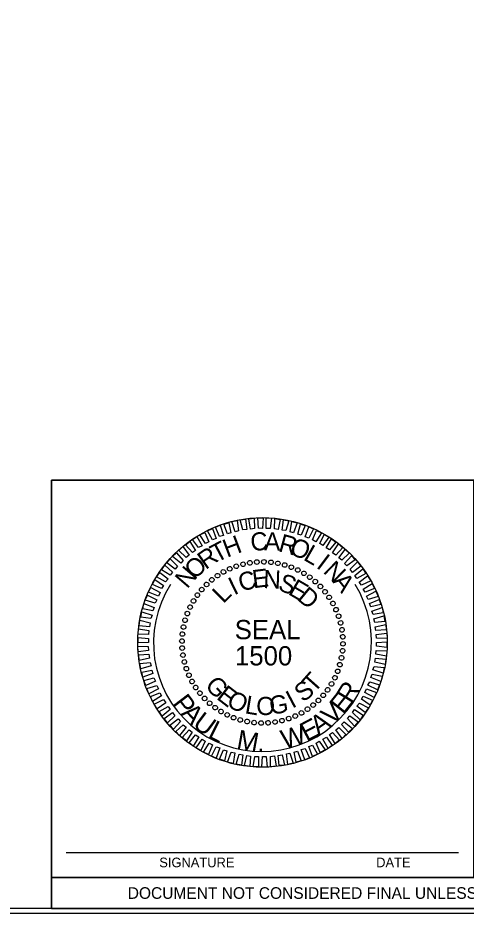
# Model space of a CAD drawing. Extents: x 265553 to 275568, y 168312 to 173522.
# Drawn here: x 273654 to 273933, y 172140 to 172697 of the extents above; entities that cross this region are included whole.
import ezdxf

# ---------------------------------------------------------------- set-up
doc = ezdxf.new("R2010")
doc.units = 0
for name, color, linetype in [('Geotech Sheets and Borders Cell', 7, 'Continuous'), ('Scratch_Level_0', 7, 'Continuous'), ('Scratch_Level_6', 7, 'Continuous'), ('Sheet Plot Border Inside CELL', 7, 'Continuous'), ('Sheet Professional Seal CELL', 7, 'Continuous'), ('Sheet Sticker Exception Certification CELL', 7, 'Continuous')]:
    doc.layers.add(name, color=color, linetype=linetype)

msp = doc.modelspace()

# ---------------------------------------------------------------- linework, layer by layer
at = {"layer": 'Geotech Sheets and Borders Cell'}
msp.add_line((273928.45, 172177.29), (273684.03, 172177.29), dxfattribs=at)
for points in [[(272700.69, 173192.58), (274200.69, 173192.58), (274200.69, 172142.58), (272700.69, 172142.58)], [(273674.76, 172409.27), (273937.73, 172409.27), (273937.73, 172161.9), (273674.76, 172161.9)]]:
    msp.add_lwpolyline(points, close=True, dxfattribs=at)
msp.add_lwpolyline([(274200.69, 172409.27), (273674.76, 172409.27), (273674.76, 172142.58), (274200.69, 172142.58), (274200.69, 172410.73)], dxfattribs=at)
at = {"layer": 'Scratch_Level_0'}
msp.add_ellipse((273806.24, 172308.22), major_axis=(45.09, 51.04), ratio=0.993455, start_param=1.731198, end_param=5.992706, dxfattribs=at)
at = {"layer": 'Scratch_Level_6'}
msp.add_circle((273806.24, 172308.22), 77.7, dxfattribs=at)
msp.add_circle((273806.24, 172308.22), 77.7, dxfattribs=at)
at = {"layer": 'Sheet Plot Border Inside CELL'}
msp.add_lwpolyline([(272545.53, 172139.74), (274213.19, 172139.74), (274213.19, 173195.41), (272545.53, 173195.41)], close=True, dxfattribs=at)
at = {"layer": 'Sheet Professional Seal CELL'}
for p, q in [((273789.84, 172355.72), (273789.84, 172355.72)), ((273794.04, 172356.92), (273794.04, 172356.92)), ((273798.44, 172357.72), (273798.44, 172357.72)), ((273802.74, 172358.32), (273802.74, 172358.32)), ((273807.14, 172358.42), (273807.14, 172358.42)), ((273811.54, 172358.12), (273811.54, 172358.12)), ((273815.84, 172357.42), (273815.84, 172357.42)), ((273820.04, 172356.52), (273820.04, 172356.52)), ((273824.24, 172355.12), (273824.24, 172355.12)), ((273778.14, 172349.82), (273778.14, 172349.82)), ((273781.94, 172352.12), (273781.94, 172352.12)), ((273785.84, 172354.12), (273785.84, 172354.12)), ((273828.24, 172353.32), (273828.24, 172353.32)), ((273832.14, 172351.32), (273832.14, 172351.32)), ((273771.34, 172344.32), (273771.34, 172344.32)), ((273774.64, 172347.32), (273774.64, 172347.32)), ((273835.74, 172348.82), (273835.74, 172348.82)), ((273839.24, 172346.12), (273839.24, 172346.12)), ((273768.34, 172341.22), (273768.34, 172341.22)), ((273842.34, 172343.12), (273842.34, 172343.12)), ((273845.34, 172339.82), (273845.34, 172339.82)), ((273763.14, 172334.12), (273763.14, 172334.12)), ((273765.64, 172337.72), (273765.64, 172337.72)), ((273847.84, 172336.32), (273847.84, 172336.32)), ((273850.14, 172332.52), (273850.14, 172332.52)), ((273761.14, 172330.22), (273761.14, 172330.22)), ((273852.14, 172328.62), (273852.14, 172328.62)), ((273757.94, 172322.02), (273757.94, 172322.02)), ((273759.34, 172326.22), (273759.34, 172326.22)), ((273853.74, 172324.62), (273853.74, 172324.62)), ((273757.04, 172317.82), (273757.04, 172317.82)), ((273854.94, 172320.42), (273854.94, 172320.42)), ((273855.74, 172316.02), (273855.74, 172316.02)), ((273756.34, 172313.52), (273756.34, 172313.52)), ((273856.34, 172311.72), (273856.34, 172311.72)), ((273756.04, 172309.12), (273756.04, 172309.12)), ((273756.14, 172304.72), (273756.14, 172304.72)), ((273856.44, 172307.32), (273856.44, 172307.32)), ((273756.74, 172300.42), (273756.74, 172300.42)), ((273856.14, 172302.92), (273856.14, 172302.92)), ((273757.54, 172296.02), (273757.54, 172296.02)), ((273854.54, 172294.42), (273854.54, 172294.42)), ((273855.44, 172298.62), (273855.44, 172298.62)), ((273758.74, 172291.82), (273758.74, 172291.82)), ((273760.34, 172287.82), (273760.34, 172287.82)), ((273853.14, 172290.22), (273853.14, 172290.22)), ((273762.34, 172283.92), (273762.34, 172283.92)), ((273849.34, 172282.32), (273849.34, 172282.32)), ((273851.34, 172286.22), (273851.34, 172286.22)), ((273764.64, 172280.12), (273764.64, 172280.12)), ((273846.84, 172278.72), (273846.84, 172278.72)), ((273767.14, 172276.62), (273767.14, 172276.62)), ((273770.14, 172273.32), (273770.14, 172273.32)), ((273841.14, 172272.12), (273841.14, 172272.12)), ((273844.14, 172275.22), (273844.14, 172275.22)), ((273773.24, 172270.32), (273773.24, 172270.32)), ((273776.74, 172267.62), (273776.74, 172267.62)), ((273834.34, 172266.62), (273834.34, 172266.62)), ((273837.84, 172269.12), (273837.84, 172269.12)), ((273780.34, 172265.12), (273780.34, 172265.12)), ((273784.24, 172263.12), (273784.24, 172263.12)), ((273788.24, 172261.32), (273788.24, 172261.32)), ((273792.44, 172259.92), (273792.44, 172259.92)), ((273822.64, 172260.72), (273822.64, 172260.72)), ((273826.64, 172262.32), (273826.64, 172262.32)), ((273830.54, 172264.32), (273830.54, 172264.32)), ((273796.64, 172259.02), (273796.64, 172259.02)), ((273800.94, 172258.32), (273800.94, 172258.32)), ((273805.34, 172258.02), (273805.34, 172258.02)), ((273809.74, 172258.12), (273809.74, 172258.12)), ((273814.04, 172258.72), (273814.04, 172258.72)), ((273818.44, 172259.52), (273818.44, 172259.52))]:
    msp.add_line(p, q, dxfattribs=at)
for points in [[(273784.44, 172375.82), (273782.14, 172381.82), (273785.24, 172382.72), (273786.54, 172376.52)], [(273789.24, 172377.12), (273787.14, 172383.42), (273790.54, 172384.12), (273791.34, 172377.62)], [(273794.04, 172378.22), (273792.44, 172384.62), (273795.74, 172384.92), (273796.44, 172378.52)], [(273798.84, 172378.82), (273797.74, 172385.22), (273801.14, 172385.62), (273801.24, 172379.12)], [(273803.84, 172379.32), (273803.34, 172385.82), (273806.64, 172385.72), (273806.24, 172379.22)], [(273808.64, 172379.22), (273808.64, 172385.72), (273811.94, 172385.62), (273811.04, 172379.12)], [(273813.64, 172378.92), (273814.04, 172385.42), (273817.34, 172384.82), (273816.04, 172378.52)], [(273818.44, 172378.12), (273819.34, 172384.52), (273822.64, 172384.02), (273820.84, 172377.82)], [(273823.54, 172377.02), (273824.54, 172383.52), (273827.94, 172382.72), (273825.64, 172376.52)], [(273775.14, 172372.12), (273771.94, 172377.72), (273775.04, 172379.12), (273777.34, 172373.02)], [(273779.54, 172374.22), (273776.94, 172380.02), (273779.94, 172381.22), (273782.04, 172374.82)], [(273828.34, 172375.72), (273829.84, 172381.92), (273832.94, 172380.92), (273830.44, 172375.02)], [(273832.84, 172373.92), (273835.14, 172380.22), (273837.94, 172379.02), (273835.14, 172373.22)], [(273837.34, 172372.02), (273839.84, 172377.92), (273842.94, 172376.52), (273839.54, 172370.92)], [(273766.44, 172367.22), (273762.74, 172372.32), (273765.34, 172374.22), (273768.64, 172368.42)], [(273770.84, 172369.72), (273767.14, 172375.12), (273770.24, 172376.72), (273772.74, 172370.92)], [(273841.94, 172369.72), (273844.64, 172375.42), (273847.64, 172373.72), (273843.84, 172368.52)], [(273845.84, 172367.02), (273849.34, 172372.82), (273851.94, 172370.72), (273848.04, 172365.82)], [(273758.64, 172361.12), (273754.24, 172365.52), (273756.64, 172367.92), (273760.54, 172362.52)], [(273762.64, 172364.22), (273758.34, 172369.02), (273761.04, 172371.12), (273764.54, 172365.52)], [(273849.94, 172364.02), (273853.64, 172369.52), (273856.24, 172367.32), (273851.84, 172362.62)], [(273853.74, 172360.92), (273857.84, 172366.12), (273860.24, 172363.72), (273855.64, 172359.42)], [(273751.84, 172353.82), (273746.64, 172357.72), (273748.84, 172360.32), (273753.24, 172355.62)], [(273755.34, 172357.62), (273750.24, 172361.72), (273752.74, 172364.02), (273756.94, 172359.22)], [(273857.34, 172357.42), (273861.64, 172362.12), (273864.04, 172359.72), (273858.84, 172355.82)], [(273748.84, 172350.02), (273743.44, 172353.42), (273745.34, 172356.32), (273750.14, 172351.92)], [(273860.84, 172353.82), (273865.44, 172358.32), (273867.54, 172355.62), (273862.24, 172351.82)], [(273745.84, 172346.02), (273740.24, 172349.02), (273742.24, 172351.82), (273747.44, 172347.82)], [(273863.84, 172349.92), (273868.74, 172354.12), (273870.64, 172351.22), (273865.04, 172348.02)], [(273866.44, 172345.82), (273871.74, 172349.62), (273873.64, 172346.62), (273867.84, 172343.82)], [(273743.44, 172341.72), (273737.74, 172344.22), (273739.24, 172347.32), (273744.64, 172343.62)], [(273869.04, 172341.42), (273874.64, 172344.92), (273875.94, 172341.82), (273870.24, 172339.52)], [(273741.44, 172337.12), (273735.24, 172339.42), (273736.74, 172342.52), (273742.44, 172339.32)], [(273871.04, 172337.12), (273876.94, 172340.12), (273878.24, 172336.92), (273872.04, 172334.92)], [(273737.94, 172327.92), (273731.74, 172329.22), (273732.44, 172332.52), (273738.74, 172330.02)], [(273739.44, 172332.72), (273733.24, 172334.52), (273734.54, 172337.62), (273740.54, 172334.82)], [(273872.84, 172332.42), (273878.94, 172335.02), (273880.04, 172331.92), (273873.84, 172330.32)], [(273736.64, 172323.12), (273730.44, 172323.92), (273731.14, 172327.32), (273737.44, 172325.22)], [(273874.44, 172327.62), (273880.84, 172329.92), (273881.44, 172326.62), (273875.14, 172325.52)], [(273735.84, 172318.02), (273729.44, 172318.62), (273729.84, 172322.02), (273736.34, 172320.42)], [(273875.64, 172322.82), (273881.94, 172324.72), (273882.54, 172321.32), (273876.24, 172320.72)], [(273735.34, 172313.22), (273728.84, 172313.42), (273729.04, 172316.72), (273735.54, 172315.62)], [(273876.54, 172318.02), (273883.04, 172319.42), (273883.34, 172316.02), (273876.94, 172315.62)], [(273735.24, 172308.22), (273728.74, 172307.92), (273728.74, 172311.32), (273735.24, 172310.62)], [(273877.14, 172313.22), (273883.64, 172314.02), (273883.84, 172310.62), (273877.34, 172310.82)], [(273735.34, 172303.22), (273728.84, 172302.42), (273728.64, 172305.82), (273735.14, 172305.62)], [(273877.24, 172308.22), (273883.74, 172308.52), (273883.74, 172305.12), (273877.24, 172305.82)], [(273735.94, 172298.42), (273729.44, 172297.02), (273729.14, 172300.42), (273735.54, 172300.82)], [(273877.14, 172303.22), (273883.64, 172303.02), (273883.44, 172299.72), (273876.94, 172300.82)], [(273736.84, 172293.62), (273730.54, 172291.72), (273729.94, 172295.12), (273736.24, 172295.72)], [(273876.64, 172298.42), (273883.04, 172297.82), (273882.64, 172294.42), (273876.14, 172296.02)], [(273738.04, 172288.82), (273731.64, 172286.52), (273731.04, 172289.82), (273737.34, 172290.92)], [(273874.54, 172288.52), (273880.74, 172287.22), (273880.04, 172283.92), (273873.74, 172286.42)], [(273875.84, 172293.32), (273882.04, 172292.52), (273881.34, 172289.12), (273875.04, 172291.22)], [(273739.64, 172284.02), (273733.54, 172281.42), (273732.44, 172284.52), (273738.64, 172286.12)], [(273873.04, 172283.72), (273879.24, 172281.92), (273877.94, 172278.82), (273871.94, 172281.62)], [(273741.44, 172279.32), (273735.54, 172276.32), (273734.24, 172279.52), (273740.44, 172281.52)], [(273743.44, 172275.02), (273737.84, 172271.52), (273736.54, 172274.62), (273742.24, 172276.92)], [(273871.04, 172279.32), (273877.24, 172277.02), (273875.74, 172273.92), (273870.04, 172277.12)], [(273746.04, 172270.62), (273740.74, 172266.82), (273738.84, 172269.82), (273744.64, 172272.62)], [(273869.04, 172274.72), (273874.74, 172272.22), (273873.24, 172269.12), (273867.84, 172272.82)], [(273748.64, 172266.52), (273743.74, 172262.32), (273741.84, 172265.22), (273747.44, 172268.42)], [(273863.64, 172266.42), (273869.04, 172263.02), (273867.14, 172260.12), (273862.34, 172264.52)], [(273866.64, 172270.42), (273872.24, 172267.42), (273870.24, 172264.62), (273865.04, 172268.62)], [(273751.64, 172262.62), (273747.04, 172258.12), (273744.94, 172260.82), (273750.24, 172264.62)], [(273755.14, 172259.02), (273750.84, 172254.32), (273748.44, 172256.72), (273753.64, 172260.62)], [(273860.64, 172262.62), (273865.84, 172258.72), (273863.64, 172256.12), (273859.24, 172260.82)], [(273758.74, 172255.52), (273754.64, 172250.32), (273752.24, 172252.72), (273756.84, 172257.02)], [(273853.84, 172255.32), (273858.24, 172250.92), (273855.84, 172248.52), (273851.94, 172253.92)], [(273857.14, 172258.82), (273862.24, 172254.72), (273859.74, 172252.42), (273855.54, 172257.22)], [(273762.54, 172252.42), (273758.84, 172246.92), (273756.24, 172249.12), (273760.64, 172253.82)], [(273766.64, 172249.42), (273763.14, 172243.62), (273760.54, 172245.72), (273764.44, 172250.62)], [(273846.04, 172249.22), (273849.74, 172244.12), (273847.14, 172242.22), (273843.84, 172248.02)], [(273849.84, 172252.22), (273854.14, 172247.42), (273851.44, 172245.32), (273847.94, 172250.92)], [(273770.54, 172246.72), (273767.84, 172241.02), (273764.84, 172242.72), (273768.64, 172247.92)], [(273775.14, 172244.42), (273772.64, 172238.52), (273769.54, 172239.92), (273772.94, 172245.52)], [(273779.64, 172242.52), (273777.34, 172236.22), (273774.54, 172237.42), (273777.34, 172243.22)], [(273837.34, 172244.32), (273840.54, 172238.72), (273837.44, 172237.32), (273835.14, 172243.42)], [(273841.64, 172246.72), (273845.34, 172241.32), (273842.24, 172239.72), (273839.74, 172245.52)], [(273784.14, 172240.72), (273782.64, 172234.52), (273779.54, 172235.52), (273782.04, 172241.42)], [(273788.94, 172239.42), (273787.94, 172232.92), (273784.54, 172233.72), (273786.84, 172239.92)], [(273794.04, 172238.32), (273793.14, 172231.92), (273789.84, 172232.42), (273791.64, 172238.62)], [(273798.84, 172237.52), (273798.44, 172231.02), (273795.14, 172231.62), (273796.44, 172237.92)], [(273818.44, 172238.22), (273820.04, 172231.82), (273816.74, 172231.52), (273816.04, 172237.92)], [(273823.24, 172239.32), (273825.34, 172233.02), (273821.94, 172232.32), (273821.14, 172238.82)], [(273828.04, 172240.62), (273830.34, 172234.62), (273827.24, 172233.72), (273825.94, 172239.92)], [(273832.94, 172242.22), (273835.54, 172236.42), (273832.54, 172235.22), (273830.44, 172241.62)], [(273803.84, 172237.22), (273803.84, 172230.72), (273800.54, 172230.82), (273801.44, 172237.32)], [(273808.64, 172237.12), (273809.14, 172230.62), (273805.84, 172230.72), (273806.24, 172237.22)], [(273813.64, 172237.62), (273814.74, 172231.22), (273811.34, 172230.82), (273811.24, 172237.32)]]:
    msp.add_lwpolyline(points, close=True, dxfattribs=at)
for centre, major_axis in [((273785.84, 172354.05), (-0.59, 1.32)), ((273789.91, 172355.65), (-0.47, 1.36)), ((273794.11, 172356.89), (-0.35, 1.4)), ((273798.4, 172357.76), (-0.23, 1.42)), ((273802.74, 172358.26), (-0.1, 1.44)), ((273807.12, 172358.37), (0.03, 1.44)), ((273811.49, 172358.11), (0.15, 1.43)), ((273815.81, 172357.46), (0.27, 1.41)), ((273820.07, 172356.44), (0.4, 1.38)), ((273824.22, 172355.05), (0.52, 1.34)), ((273828.23, 172353.31), (0.63, 1.29)), ((273778.19, 172349.81), (-0.81, 1.19)), ((273781.93, 172352.09), (-0.7, 1.26)), ((273832.08, 172351.22), (0.74, 1.23)), ((273835.73, 172348.8), (0.85, 1.16)), ((273771.4, 172344.3), (-1, 1.04)), ((273774.68, 172347.2), (-0.91, 1.12)), ((273839.15, 172346.08), (0.94, 1.09)), ((273842.33, 172343.07), (1.04, 1)), ((273765.66, 172337.7), (-1.16, 0.85)), ((273768.39, 172341.13), (-1.09, 0.94)), ((273845.23, 172339.79), (1.12, 0.91)), ((273763.25, 172334.06), (-1.23, 0.74)), ((273847.83, 172336.27), (1.19, 0.81)), ((273850.11, 172332.54), (1.26, 0.7)), ((273759.42, 172326.2), (-1.34, 0.52)), ((273761.16, 172330.21), (-1.29, 0.63)), ((273852.07, 172328.62), (1.32, 0.59)), ((273758.03, 172322.05), (-1.38, 0.4)), ((273853.67, 172324.55), (1.36, 0.47)), ((273854.91, 172320.36), (1.4, 0.35)), ((273757.01, 172317.79), (-1.41, 0.27)), ((273855.79, 172316.07), (1.42, 0.23)), ((273756.09, 172309.1), (-1.44, 0.03)), ((273756.36, 172313.46), (-1.43, 0.15)), ((273856.28, 172311.72), (1.44, 0.1)), ((273756.21, 172304.72), (-1.44, -0.1)), ((273856.4, 172307.35), (1.44, -0.03)), ((273756.7, 172300.37), (-1.42, -0.23)), ((273855.48, 172298.65), (1.41, -0.27)), ((273856.13, 172302.98), (1.43, -0.15)), ((273757.57, 172296.09), (-1.4, -0.35)), ((273758.82, 172291.89), (-1.36, -0.47)), ((273854.46, 172294.4), (1.38, -0.4)), ((273760.42, 172287.82), (-1.32, -0.59)), ((273851.33, 172286.23), (1.29, -0.63)), ((273853.07, 172290.25), (1.34, -0.52)), ((273762.37, 172283.9), (-1.26, -0.7)), ((273849.24, 172282.39), (1.23, -0.74)), ((273764.66, 172280.17), (-1.19, -0.81)), ((273767.26, 172276.65), (-1.12, -0.91)), ((273844.1, 172275.31), (1.09, -0.94)), ((273846.82, 172278.74), (1.16, -0.85)), ((273770.16, 172273.38), (-1.04, -1)), ((273773.34, 172270.37), (-0.94, -1.09)), ((273841.09, 172272.14), (1, -1.04)), ((273776.76, 172267.64), (-0.85, -1.16)), ((273780.41, 172265.23), (-0.74, -1.23)), ((273830.56, 172264.35), (0.7, -1.26)), ((273834.29, 172266.64), (0.81, -1.19)), ((273837.81, 172269.24), (0.91, -1.12)), ((273784.26, 172263.14), (-0.63, -1.29)), ((273788.27, 172261.39), (-0.52, -1.34)), ((273792.42, 172260), (-0.4, -1.38)), ((273796.67, 172258.98), (-0.27, -1.41)), ((273814.09, 172258.68), (0.23, -1.42)), ((273818.38, 172259.55), (0.35, -1.4)), ((273822.57, 172260.79), (0.47, -1.36)), ((273826.65, 172262.4), (0.59, -1.32)), ((273801, 172258.34), (-0.15, -1.43)), ((273805.37, 172258.07), (-0.03, -1.44)), ((273809.74, 172258.18), (0.1, -1.44))]:
    msp.add_ellipse(centre, major_axis=major_axis, ratio=0.999708, dxfattribs=at)
at = {"layer": 'Sheet Sticker Exception Certification CELL'}
for p, q in [((273674.76, 172161.9), (274200.69, 172161.9)), ((273674.76, 172142.58), (273674.76, 172161.9)), ((273674.76, 172142.58), (274200.69, 172142.58))]:
    msp.add_line(p, q, dxfattribs=at)

# ---------------------------------------------------------------- texts
at = {"layer": 'Geotech Sheets and Borders Cell'}
for s, p in [('SIGNATURE', (273741.96, 172168.28)), ('DATE', (273877.08, 172168.28))]:
    msp.add_text(s, height=6, dxfattribs=at).set_placement(p)
at = {"layer": 'Sheet Professional Seal CELL'}
for s, height, rotation, p in [('C', 11.28, 6.2199, (273799.34, 172364.92)), ('T', 11.28, 27.8198, (273777.64, 172357.62)), ('H', 11.28, 20.6195, (273784.14, 172360.92)), ('A', 11.28, 359.0203, (273807.24, 172365.52)), ('R', 11.28, 344.6211, (273815.64, 172365.12)), ('O', 11.28, 337.4212, (273822.34, 172363.62)), ('R', 11.28, 35.0205, (273770.84, 172353.22)), ('L', 11.28, 330.2209, (273831.14, 172359.92)), ('O', 11.28, 42.2217, (273763.94, 172347.02)), ('I', 11.28, 323.0201, (273839.24, 172355.12)), ('N', 11.28, 49.4235, (273759.34, 172341.22)), ('N', 11.28, 315.8189, (273843.54, 172352.02)), ('C', 11.28, 16.6111, (273793.07, 172339.62)), ('E', 11.28, 7.2556, (273800.56, 172341.91)), ('N', 11.28, 357.9004, (273806.63, 172342.07)), ('S', 11.28, 339.1896, (273815.3, 172341.06)), ('A', 11.28, 308.6172, (273849.44, 172346.12)), ('I', 11.28, 25.967, (273788.53, 172337.4)), ('E', 11.28, 329.8335, (273821.67, 172338.51)), ('L', 11.28, 44.6812, (273781.83, 172332)), ('D', 11.28, 320.4766, (273827.26, 172335.13)), ('T', 11.28, 48.3432, (273838.38, 172276.3)), ('G', 11.28, 312.9799, (273769.89, 172280.94)), ('S', 11.28, 37.1844, (273831.46, 172270.58)), ('R', 12, 58.4746, (273861.82, 172269.4)), ('E', 11.28, 322.3369, (273777.06, 172273.46)), ('O', 11.28, 331.6932, (273783.11, 172269.09)), ('I', 11.28, 27.8271, (273824.7, 172266.86)), ('E', 12, 51.4825, (273856.6, 172262.85)), ('P', 12, 307.2789, (273749.64, 172270.17)), ('L', 11.28, 350.4042, (273794.83, 172264.18)), ('O', 11.28, 359.7594, (273802.36, 172263.06)), ('G', 11.28, 9.1148, (273811.46, 172263.15)), ('V', 12, 43.3675, (273849.61, 172256.11)), ('A', 12, 314.4055, (273754.71, 172263.51)), ('U', 12, 323.2702, (273762.11, 172256.19)), ('E', 12, 27.6676, (273833.72, 172246.17)), ('A', 12, 34.6703, (273841.13, 172250.06)), ('L', 12, 333.2297, (273771.65, 172249.43)), ('W', 12, 15.2925, (273819.69, 172241.62)), ('M', 12, 349.7003, (273789.59, 172242.15)), ('.', 12, 1.1804, (273803.02, 172240.24))]:
    msp.add_text(s, height=height, rotation=rotation, dxfattribs=at).set_placement(p)
for s, p in [('SEAL', (273788.95, 172310.22)), ('1500', (273789.09, 172293.91))]:
    msp.add_text(s, height=11.996, dxfattribs=at).set_placement(p)
at = {"layer": 'Sheet Sticker Exception Certification CELL'}
msp.add_text('DOCUMENT NOT CONSIDERED FINAL UNLESS ALL SIGNATURES COMPLETED', height=7.2302, dxfattribs=at).set_placement((273722.32, 172148.62))

doc.saveas('drawing.dxf')
